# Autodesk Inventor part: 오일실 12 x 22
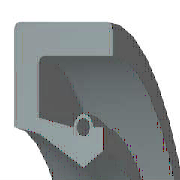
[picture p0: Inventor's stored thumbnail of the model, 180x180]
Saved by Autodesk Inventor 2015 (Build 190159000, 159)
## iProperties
IsCustomPart: 0
Created: 2015-10
Part Number: 오일실 12 x 22
Material: Rubber
Description: 오일-실
Document SubType Name: Modeling
Standard: KS B 2804
Designer: mdu
Standards Organization: KS
Language: ko-KR
Size Designation: S - 12 22 7
Categories: <MemberInstance><Categories><Category DisplayName="샤프트 부품" InternalName="7f7aeb1f-a693-4053-b835-cee3144e0d98" Mnemonic="SHFT"><Category DisplayName="실링" Intern
Density: 0.93 g/cm^3
Appearance: Rubber - Black - Version 1.1
Author: mdu
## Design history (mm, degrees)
revolve "본체" stored, may be unused: angle "d17" = 90 deg
revolve "스프링1" stored, may be unused: angle "d18" = 90 deg
body "Solid1"
sketch "스케치1"
  geometry: L1 (0, 11)-(7, 11); L2 (7, 11)-(7, 9.75); L3 (7, 9.75)-(1.75, 9.75); L4 (0, 11)-(0, 8.1); L5 (0, 8.1)-(1.75, 7.75); L6 (1.75, 7.75)-(4.9, 6); L7 (4.9, 6)-(0, 6); L8 (6.3, 6.875)-(6.3, 8.1); L9 (0, 0)-(9.586, 0) reference; L10 (4.9, 6)-(6.3, 6.875); L11 (0, 18)-(0, -3) reference; L12 (-1.917, 0)-(11.503, 0) reference; L13 (4.2, 8.1)-(1.75, 8.59); L14 (1.75, 8.59)-(1.75, 9.75); L15 (6.3, 8.1)-(5.6, 8.1); C1 r 0.455 at (4.9, 8.1); A1 r 0.7 centre (4.9, 8.1) between (5.6, 8.1) and (4.2, 8.1)
  constraints: 26 end point, 5 horizontal alignment, 4 perpendicular, 2 centre point, 2 collinear, 2 horizontal, 2 parallel, 2 point on circle, 2 point on line, 2 vertical alignment, 1 coincident
  dimensions: "d0" = 22 diameter of L1 L9 (= SD2); "d1" = 13.75 diameter of L8.start L9 (= ABDM); "d2" = 1.25 distance of L1.end L2.end (computed from SD); "d3" = 0.91 diameter of C1 (= SPDI); "d4" = 1.4 diameter of A1 (= SPDA); "d5" = 12 diameter of L6.end L9 (= NND); "d6" = 15.5 diameter of L5.end L9 (= TKDM); "d7" = 16.2 diameter of L4.end L9 (= HLDM); "d8" = 4.9 distance from line of C1.centre L4 (= SPDST); "d9" = 6.3 distance between parallel lines of L8 L4 (= SDI); "d10" = 7 distance between parallel lines of L2 L4 (= SWDT); "d12" = 1.75 distance between parallel lines of L14 L4 (= SD)
fillet "모깎기1" dims "d11" = 0.3 (= RR)
other parameters: "SD2" = 22 [user parameter; used in 1 equation term], "SWDT" = 7 [user parameter; used in 1 equation term], "RR" = 0.3 [user parameter; used in 1 equation term], "SD" = 1.75 [user parameter; used in 2 equation terms], "NND" = 12 [user parameter; used in 1 equation term], "SPDA" = 1.4 [user parameter; used in 1 equation term], "SPDI" = 0.91 [user parameter; used in 1 equation term], "TKDM" = 15.5 [user parameter; used in 1 equation term], "HLDM" = 16.2 [user parameter; used in 1 equation term], "ABDM" = 13.75 [user parameter; used in 1 equation term], "SDI" = 6.3 [user parameter; used in 1 equation term], "SPDST" = 4.9 [user parameter; used in 1 equation term], "d13" = 0, "d14" = 0, "d15" = 0, "LAB" = 0.35 [user parameter]
